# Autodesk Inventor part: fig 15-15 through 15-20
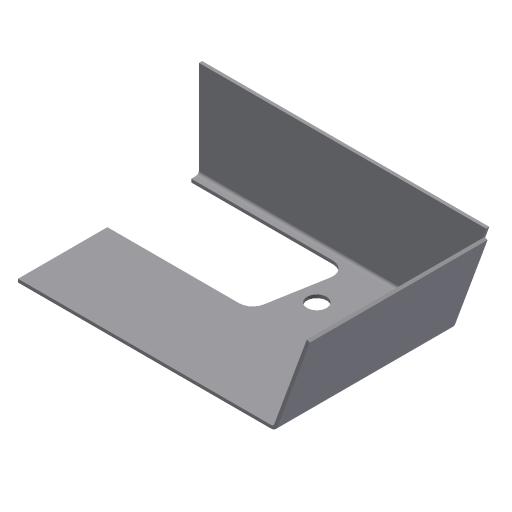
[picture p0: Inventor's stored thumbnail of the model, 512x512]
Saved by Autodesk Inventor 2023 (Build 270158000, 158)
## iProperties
Created: 2005-03
Part Number: fig 15-15 through 15-20
Document SubType Name: Sheet Metal
Designer: CADCIM
Manufacturer: Standard
Standards Organization: Custom
Density: 1 g/cm^3
Sheet Metal Rule: Default
Material: Generic
Flat Pattern Width: 4.32624 cm
Flat Pattern Length: 5.50678 cm
Flat Pattern Area: 23.8236 cm^2
Sheet Metal Width: 43.262 mm
Sheet Metal Length: 55.068 mm
Sheet Metal Area: 2382.364 mm^2
Appearance: Default
Author: CADCIM
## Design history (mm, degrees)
node "Face2"
  sketch "Sketch1" dims "d32" = 0.5 (= BendRadius), "CornerReliefSize" = 2 (= 4 x Thickness)
    geometry: L1 (-36, -8.631)-(4.238, -8.631); L2 (4.238, -8.631)-(4.238, 20); L3 (4.238, 20)-(-36, 20); L4 (-36, 20)-(-36, -8.631)
    constraints: 8 end point, 2 parallel, 1 horizontal, 1 perpendicular
node "Flange3"
node "Flange2"
feature "Corner2" dims "d36" = 2 (= CornerReliefSize), "d37" = 0.5 (= BendRadius), "d38" = 0.5 (= Thickness), "d39" = 0, "d49" = 0.5 (= Thickness)
sketch "Sketch5"
  geometry: 1 further point
sketch "Sketch6"
  geometry: 3 further points
feature "iFeature14:1" sketch "Sketch6" dims "d43" = 3.048 (derived), "d45" = 16.6624 (derived)
body "Solid1"
face "Plate2" dims "d49" = 0.5 (= Thickness), "CornerReliefSize" = 2 (= 4 x Thickness)
sketch "Sketch3" dims "BendReliefDepth" = 0.25 (= 0.5 x Thickness)
  geometry: L1 (39.356, 0)-(39.356, 15); L2 (39.356, 15)-(0, 15); 1 other entity
  constraints: 4 end point, 4 other
face "Plate4" dims "d18" = 0.5 (= BendReliefWidth), "d20" = 1 (= MinimumRemnant), "d22" = 15, "d23" = 90 deg, "d24" = 0.5 (= BendRadius), "d32" = 0.5 (= BendRadius), "d49" = 0.5 (= Thickness), "BendReliefDepth" = 0.25 (= 0.5 x Thickness), "CornerReliefSize" = 2 (= 4 x Thickness)
bend "Bend2" dims "d18" = 0.5 (= BendReliefWidth), "d19" = 0.25 (= BendReliefDepth), "d20" = 1 (= MinimumRemnant), "d21" = 0.5 (= BendRadius), "d22" = 15, "d23" = 90 deg, "d24" = 0.5 (= BendRadius), "d49" = 0.5 (= Thickness), "SeamGap" = 0.01
node "FlatPattern"
sketch "Sketch4" dims "d32" = 0.5 (= BendRadius)
  geometry: L1 (28.631, 0)-(28.631, 15); L2 (28.631, 15)-(0, 15); 1 other entity
  constraints: 4 end point, 4 other
face "Plate5" dims "d29" = 0.5 (= BendReliefWidth), "d31" = 1 (= MinimumRemnant), "d32" = 0.5 (= BendRadius), "d33" = 15, "d34" = 70 deg, "d35" = 0.5 (= BendRadius), "d49" = 0.5 (= Thickness), "CornerReliefSize" = 2 (= 4 x Thickness)
bend "Bend3" dims "d29" = 0.5 (= BendReliefWidth), "d30" = 0.25 (= BendReliefDepth), "d31" = 1 (= MinimumRemnant), "d32" = 0.5 (= BendRadius), "d33" = 15, "d34" = 70 deg, "d35" = 0.5 (= BendRadius), "d49" = 0.5 (= Thickness), "SeamGap" = 0.01
feature "FlatPatternExtrusion2" dims "d0" = 0.5 (derived)
other parameters: "Thickness" = 0.5, "BendRadius" = 0.5 (= Thickness), "BendReliefWidth" = 0.5 (= Thickness), "MinimumRemnant" = 1 (= 2 x Thickness), "TransitionRadius" = 0.5 (= BendRadius), "d0" = 0.5 (= BendRadius), "d10" = 0.5 (= BendRadius), "JacobiRadiusSize" = 0.5 (= Thickness), "GapSize" = 0.5 (= Thickness), "d48" = 0
